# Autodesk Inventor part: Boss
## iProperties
Created: 2008-12
Part Number: Boss
Document SubType Name: Modeling
Designer: Ed O'Halloran
Density: 1 g/cm^3
Author: Ed O'Halloran
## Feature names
1. Extrusion1
2. Revolution1
3. Fillet1
4. Revolution2
5. Fillet2
6. Extrusion2
7. Extrusion3
8. FaceDraft1
9. Fillet4
10. Lens Retaining Ring [Extrusion]
11. Lens Screw Mount [Extrusion]
12. Fillet7
13. Extrusion10
14. Extrusion11
15. Circular Pattern1
16. Fillet8
